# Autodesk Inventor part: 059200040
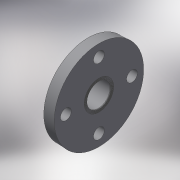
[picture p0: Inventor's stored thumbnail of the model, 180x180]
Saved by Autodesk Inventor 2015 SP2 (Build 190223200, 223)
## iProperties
Created: 2017-10
Part Number: 059200040
Material: Generic
Description: PLASSON FIXED FLANGE-CEM PVC 40
Document SubType Name: Modeling
Designer: KIM
Mass: 213.569 g
Surface Area: 419.874 cm^2
Volume: 213.569 cm^3
Density: 1 g/cm^3
Appearance: Default
Author: KIM
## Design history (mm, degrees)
derived "059200.ipt"
feature "Solid1::059200.ipt"
tag "TaggingFeature1"
body "Solid1"
other parameters: "d0" = 27, "d3" = 138.6, "d14" = 18, "d16" = 27, "d17" = 0, "d19" = 360 deg, "d21" = 26, "d23" = 38, "d24" = 48, "d25" = 0.4, "d26" = 0.7, "d27" = 0.7, "d28" = 0.7, "d29" = 0.7, "d30" = 0.7, "d31" = 0.7, "d32" = 0.28, "d33" = 0, "d34" = 16, "H_" = 27, "S_" = 18, "l_" = 26, "H_1" = 16
